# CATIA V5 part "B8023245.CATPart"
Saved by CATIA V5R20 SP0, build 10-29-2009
Part number: B8023245
Revision: 8
Definition: design
Nomenclature: B8023245
Source: made
Description: NOT SPECIFIED
Bounding box of the stored display mesh (mm): x -28 to 28, y -28 to 28, z -12 to 45
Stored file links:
  C:\Users\Utente\Desktop\3D files B802\B8023245.CATPart
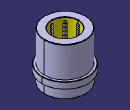
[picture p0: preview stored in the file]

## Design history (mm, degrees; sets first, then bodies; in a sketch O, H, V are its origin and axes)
Body1 "MANIFOLD_SOLID_BREP #38" (main body)
  Solid1: solid without history
Body2 "MANIFOLD_SOLID_BREP #76"
  Solid2: solid without history
Body3 "MANIFOLD_SOLID_BREP #114"
  Solid3: solid without history
Body4 "MANIFOLD_SOLID_BREP #152"
  Solid4: solid without history
Body5 "MANIFOLD_SOLID_BREP #190"
  Solid5: solid without history
Body6 "MANIFOLD_SOLID_BREP #228"
  Solid6: solid without history
Body7 "MANIFOLD_SOLID_BREP #266"
  Solid7: solid without history
Body8 "MANIFOLD_SOLID_BREP #304"
  Solid8: solid without history
Body9 "MANIFOLD_SOLID_BREP #2384"
  Solid9: solid without history
Body10 "MANIFOLD_SOLID_BREP #2422"
  Solid10: solid without history
Body11 "MANIFOLD_SOLID_BREP #2460"
  Solid11: solid without history
Body12 "MANIFOLD_SOLID_BREP #2498"
  Solid12: solid without history
Body13 "MANIFOLD_SOLID_BREP #2536"
  Solid13: solid without history
Body14 "MANIFOLD_SOLID_BREP #2574"
  Solid14: solid without history
Body15 "MANIFOLD_SOLID_BREP #2612"
  Solid15: solid without history
Body16 "MANIFOLD_SOLID_BREP #2650"
  Solid16: solid without history
Body17 "MANIFOLD_SOLID_BREP #2688"
  Solid17: solid without history
Body18 "MANIFOLD_SOLID_BREP #2726"
  Solid18: solid without history
Body19 "MANIFOLD_SOLID_BREP #2764"
  Solid19: solid without history
Body20 "MANIFOLD_SOLID_BREP #2802"
  Solid20: solid without history
Body21 "MANIFOLD_SOLID_BREP #2840"
  Solid21: solid without history
Body22 "MANIFOLD_SOLID_BREP #2878"
  Solid22: solid without history
Body23 "MANIFOLD_SOLID_BREP #2916"
  Solid23: solid without history
Body24 "MANIFOLD_SOLID_BREP #2954"
  Solid24: solid without history
Body25 "MANIFOLD_SOLID_BREP #2992"
  Solid25: solid without history
Body26 "MANIFOLD_SOLID_BREP #3030"
  Solid26: solid without history
Body27 "MANIFOLD_SOLID_BREP #3068"
  Solid27: solid without history
Body28 "MANIFOLD_SOLID_BREP #3106"
  Solid28: solid without history
Body29 "MANIFOLD_SOLID_BREP #3144"
  Solid29: solid without history
Body30 "MANIFOLD_SOLID_BREP #3182"
  Solid30: solid without history
Body31 "MANIFOLD_SOLID_BREP #3220"
  Solid31: solid without history
Body32 "MANIFOLD_SOLID_BREP #3258"
  Solid32: solid without history
Body33 "MANIFOLD_SOLID_BREP #3296"
  Solid33: solid without history
Body34 "MANIFOLD_SOLID_BREP #3334"
  Solid34: solid without history
Body35 "MANIFOLD_SOLID_BREP #3372"
  Solid35: solid without history
Body36 "MANIFOLD_SOLID_BREP #3410"
  Solid36: solid without history
Body37 "MANIFOLD_SOLID_BREP #3448"
  Solid37: solid without history
Body38 "MANIFOLD_SOLID_BREP #3486"
  Solid38: solid without history
Body39 "MANIFOLD_SOLID_BREP #3524"
  Solid39: solid without history
Body40 "MANIFOLD_SOLID_BREP #3562"
  Solid40: solid without history
Body41 "MANIFOLD_SOLID_BREP #3600"
  Solid41: solid without history
Body42 "MANIFOLD_SOLID_BREP #3638"
  Solid42: solid without history
Body43 "MANIFOLD_SOLID_BREP #3676"
  Solid43: solid without history
Body44 "MANIFOLD_SOLID_BREP #3714"
  Solid44: solid without history
Body45 "MANIFOLD_SOLID_BREP #3752"
  Solid45: solid without history
Body46 "MANIFOLD_SOLID_BREP #3790"
  Solid46: solid without history
Body47 "MANIFOLD_SOLID_BREP #3828"
  Solid47: solid without history
Body48 "MANIFOLD_SOLID_BREP #3866"
  Solid48: solid without history
Body49 "MANIFOLD_SOLID_BREP #3904"
  Solid49: solid without history
Body50 "MANIFOLD_SOLID_BREP #3942"
  Solid50: solid without history
Body51 "MANIFOLD_SOLID_BREP #3980"
  Solid51: solid without history
Body52 "MANIFOLD_SOLID_BREP #4018"
  Solid52: solid without history
Body53 "MANIFOLD_SOLID_BREP #4056"
  Solid53: solid without history
Body54 "MANIFOLD_SOLID_BREP #4094"
  Solid54: solid without history
Body55 "MANIFOLD_SOLID_BREP #4132"
  Solid55: solid without history
Body56 "MANIFOLD_SOLID_BREP #4170"
  Solid56: solid without history
Body57 "MANIFOLD_SOLID_BREP #4208"
  Solid57: solid without history
Body58 "MANIFOLD_SOLID_BREP #4246"
  Solid58: solid without history
Body59 "MANIFOLD_SOLID_BREP #4284"
  Solid59: solid without history
Body60 "MANIFOLD_SOLID_BREP #4322"
  Solid60: solid without history
Body61 "MANIFOLD_SOLID_BREP #4360"
  Solid61: solid without history
Body62 "MANIFOLD_SOLID_BREP #4398"
  Solid62: solid without history
Body63 "MANIFOLD_SOLID_BREP #4436"
  Solid63: solid without history
Body64 "MANIFOLD_SOLID_BREP #4474"
  Solid64: solid without history
Body65 "MANIFOLD_SOLID_BREP #4512"
  Solid65: solid without history
Body66 "MANIFOLD_SOLID_BREP #4550"
  Solid66: solid without history
Body67 "MANIFOLD_SOLID_BREP #4588"
  Solid67: solid without history
Body68 "MANIFOLD_SOLID_BREP #4626"
  Solid68: solid without history
Body69 "MANIFOLD_SOLID_BREP #4664"
  Solid69: solid without history
Body70 "MANIFOLD_SOLID_BREP #4702"
  Solid70: solid without history
Body71 "MANIFOLD_SOLID_BREP #4740"
  Solid71: solid without history
Body72 "MANIFOLD_SOLID_BREP #4778"
  Solid72: solid without history
Body73 "MANIFOLD_SOLID_BREP #4816"
  Solid73: solid without history
Body74 "MANIFOLD_SOLID_BREP #4854"
  Solid74: solid without history
Body75 "MANIFOLD_SOLID_BREP #4892"
  Solid75: solid without history
Body76 "MANIFOLD_SOLID_BREP #4930"
  Solid76: solid without history
Body77 "MANIFOLD_SOLID_BREP #4968"
  Solid77: solid without history
Body78 "MANIFOLD_SOLID_BREP #5006"
  Solid78: solid without history
Body79 "MANIFOLD_SOLID_BREP #5044"
  Solid79: solid without history
Body80 "MANIFOLD_SOLID_BREP #5082"
  Solid80: solid without history
Body81 "MANIFOLD_SOLID_BREP #5120"
  Solid81: solid without history
Body82 "MANIFOLD_SOLID_BREP #5158"
  Solid82: solid without history
Body83 "MANIFOLD_SOLID_BREP #5196"
  Solid83: solid without history
Body84 "MANIFOLD_SOLID_BREP #5234"
  Solid84: solid without history
Body85 "MANIFOLD_SOLID_BREP #5272"
  Solid85: solid without history
Body86 "MANIFOLD_SOLID_BREP #5310"
  Solid86: solid without history
Body87 "MANIFOLD_SOLID_BREP #5348"
  Solid87: solid without history
Body88 "MANIFOLD_SOLID_BREP #5386"
  Solid88: solid without history
Body89 "MANIFOLD_SOLID_BREP #5424"
  Solid89: solid without history
Body90 "MANIFOLD_SOLID_BREP #5462"
  Solid90: solid without history
Body91 "MANIFOLD_SOLID_BREP #5500"
  Solid91: solid without history
Body92 "MANIFOLD_SOLID_BREP #5538"
  Solid92: solid without history
Body93 "MANIFOLD_SOLID_BREP #5576"
  Solid93: solid without history
Body94 "MANIFOLD_SOLID_BREP #5614"
  Solid94: solid without history
Body95 "MANIFOLD_SOLID_BREP #5652"
  Solid95: solid without history
Body96 "MANIFOLD_SOLID_BREP #5690"
  Solid96: solid without history
Body97 "MANIFOLD_SOLID_BREP #5728"
  Solid97: solid without history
